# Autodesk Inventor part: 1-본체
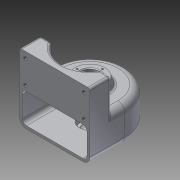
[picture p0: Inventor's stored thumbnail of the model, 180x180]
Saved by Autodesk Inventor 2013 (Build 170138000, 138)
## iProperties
Created: 2015-02
Part Number: 1-본체
Material: 알루미늄 6061
Document SubType Name: Modeling
Designer: Administrator
Density: 2.40731 g/cm^3
Mass: 511.243 g
Surface Area: 706.56 cm^2
Volume: 212.371 cm^3
Author: Administrator
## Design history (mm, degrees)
sketch "스케치1"
  geometry: L1 (-50, 0)-(-50, -50); L2 (-50, -50)-(50, -50); L3 (50, -50)-(50, 0); A1 r 50 centre (0, 0) between (50, 0) and (-50, 0); 2 further points
  constraints: 6 end point, 2 point on circle, 2 tangent, 1 centre point, 1 coincident, 1 midpoint, 1 parallel, 1 perpendicular, 1 vertical, 1 vertical alignment
  dimensions: "d0" = 50 radius of A1; "d2" = 50 distance from line of L2 point (0, 0)
extrude "돌출1" new body sketch "스케치1" distance "d3" = 50; taper "d4" = 0 deg
feature "쉘1" dims "d18" = 4
sketch "스케치2"
  geometry: L1 (-50, 0)-(-50, -50) reference; L2 (-50, -50)-(50, -50) reference; L3 (50, -50)-(50, 0) reference; L4 (-34.641, -20)-(-50, -20); L5 (-50, -20)-(-50, -50); L6 (50, -50)-(-50, -50); L7 (50, -50)-(50, -20); L8 (50, -20)-(34.641, -20); A1 r 50 centre (0, 0) between (50, 0) and (-50, 0) reference; A2 r 40 centre (0, 0) between (-34.641, -20) and (34.641, -20); 2 further points
  constraints: 10 end point, 3 perpendicular, 2 midpoint, 2 point on circle, 2 point on line, 1 centre point, 1 coincident, 1 collinear, 1 horizontal alignment
  dimensions: "d5" = 40 radius of A2; "d7" = 30 distance between parallel lines of L2 L4
extrude "돌출2" join sketch "스케치2" distance "d8" = 45; taper "d9" = 0 deg
sketch "스케치3"
  geometry: C1 r 25 at (0, 0); A1 r 40 centre (0, 0) between (-34.641, -20) and (34.641, -20) reference
  constraints: 1 centre point, 1 coincident
  dimensions: "d10" = 50 diameter of C1
extrude "돌출3" join sketch "스케치3" distance "d12" = 10; taper "d13" = -20 deg
sketch "스케치4"
  geometry: C1 r 20 at (0, 0); A1 r 50 centre (0, 0) between (50, 0) and (-50, 0) reference
  constraints: 1 centre point, 1 coincident
  dimensions: "d14" = 40 diameter of C1
extrude "돌출4" join sketch "스케치4" distance "d16" = 9; taper "d17" = 0 deg
hole "구멍1" diameter "d21" = 20; stored, may be unused: countersink angle "d25" = 90 deg, drill point angle "d27" = 0 deg; dims "d19" = 10, "d20" = 10, "d22" = 6, "d23" = 28, "d24" = 10, "d26" = 14
sketch "스케치5"
  geometry: C1 r 14 at (0, 0); A1 r 46 centre (0, 0) between (46, 0) and (-46, 0) reference
  constraints: 1 centre point, 1 coincident
  dimensions: "d28" = 28 diameter of C1
extrude "돌출5" cut sketch "스케치5" distance "d30" = 8; taper "d31" = 0 deg
hole "구멍2" diameter "d34" = 20; stored, may be unused: countersink angle "d38" = 90 deg, drill point angle "d40" = 0 deg; dims "d32" = 10, "d33" = 10, "d35" = 6, "d36" = 28, "d37" = 10, "d39" = 2
sketch "스케치6"
  geometry: L1 (0, 95)-(100, 95) reference; L2 (0, 0)-(0, 95) reference; L3 (8.25, 86)-(91.75, 86); 7 further points
  constraints: 3 vertical alignment, 2 coincident, 2 end point, 2 midpoint, 1 horizontal alignment, 1 perpendicular
  dimensions: "d41" = 83.5 distance of L3.start L3.end; "d43" = 9 distance from line of L1 point (8.25, 86); "d44" = 33 distance of point (91.75, 86) point (91.75, 53)
hole "구멍3" sketch "스케치6" at (8.25, 86), (91.75, 86), (8.25, 53), (91.75, 53) diameter "d45" = 5.134; stored, may be unused: countersink angle "d49" = 90 deg, drill point angle "d51" = 118 deg; dims "d46" = 10, "d47" = 28, "d48" = 10, "d50" = 13
sketch "스케치7"
  geometry: C1 r 14 at (0, 0) reference; C2 r 21.36 at (0, 0) reference; A1 r 18 centre (0, 0) between (0, 18) and (-18, 0); 2 further points
  constraints: 4 point on circle, 2 horizontal alignment, 2 vertical alignment, 1 centre point, 1 coincident
  dimensions: "d52" = 36 diameter of A1
hole "구멍4" sketch "스케치7" at (0, 18), (-18, 0), (0, -18), (18, 0) diameter "d54" = 2.459; stored, may be unused: countersink angle "d58" = 90 deg, drill point angle "d60" = 118 deg; dims "d55" = 6, "d56" = 28, "d57" = 10, "d59" = 9
node "작업 평면1"
sketch "스케치8"
  geometry: L1 (-50, 0)-(50, 0) reference; 3 further points
  constraints: 1 midpoint, 1 vertical alignment, 1 other
  dimensions: "d61" = 25 distance from line of L1 point (0, 25)
feature "엠보싱1" sketch "스케치8" dims "d62" = 0.5, "d63" = 0
fillet "모깎기1" dims "d64" = 0.3
chamfer "모따기1" distance "d65" = 1; stored, may be unused: second distance "d66" = 2, angle "d67" = 45 deg
fillet "모깎기2" dims "d68" = 3
fillet "모깎기3" dims "d69" = 10, "d70" = 6
fillet "모깎기4" dims "d71" = 3
node "솔리드1"
